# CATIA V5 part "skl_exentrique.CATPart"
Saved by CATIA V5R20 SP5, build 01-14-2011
Part number: skl_exentrique
Publications: "Point.1", "Point.2", "Plan_ref", "Axe_pivot_exentrique_bati", "Axe_pivot_exentrique_bielle_2"
Bounding box of the stored display mesh (mm): x -10 to 10, y 0 to 0, z 0 to 10
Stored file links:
  U:\2A\IAO\ThinkMotion\skl_exentrique.CATPart
  U:\2A\IAO\ThinkMotion\skl.CATProduct
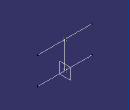
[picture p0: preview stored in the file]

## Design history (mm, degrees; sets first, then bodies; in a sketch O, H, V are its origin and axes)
Set1
  Point1: linked copy from another document
  Point2: linked copy from another document
  Plane1 "Plan_ref": linked copy from another document
Set2
  Line1: type PtPt, FirstPoint Point1, SecondPoint Point2
  Line2 "Axe_pivot_exentrique_bati": type Normal, RefPoint Point1, RefSkin Plane1, Start -10, End 10
  Line3 "Axe_pivot_exentrique_bielle_2": type Normal, RefPoint Point2, RefSkin Plane1, Start -10, End 10
Body1 (main body)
